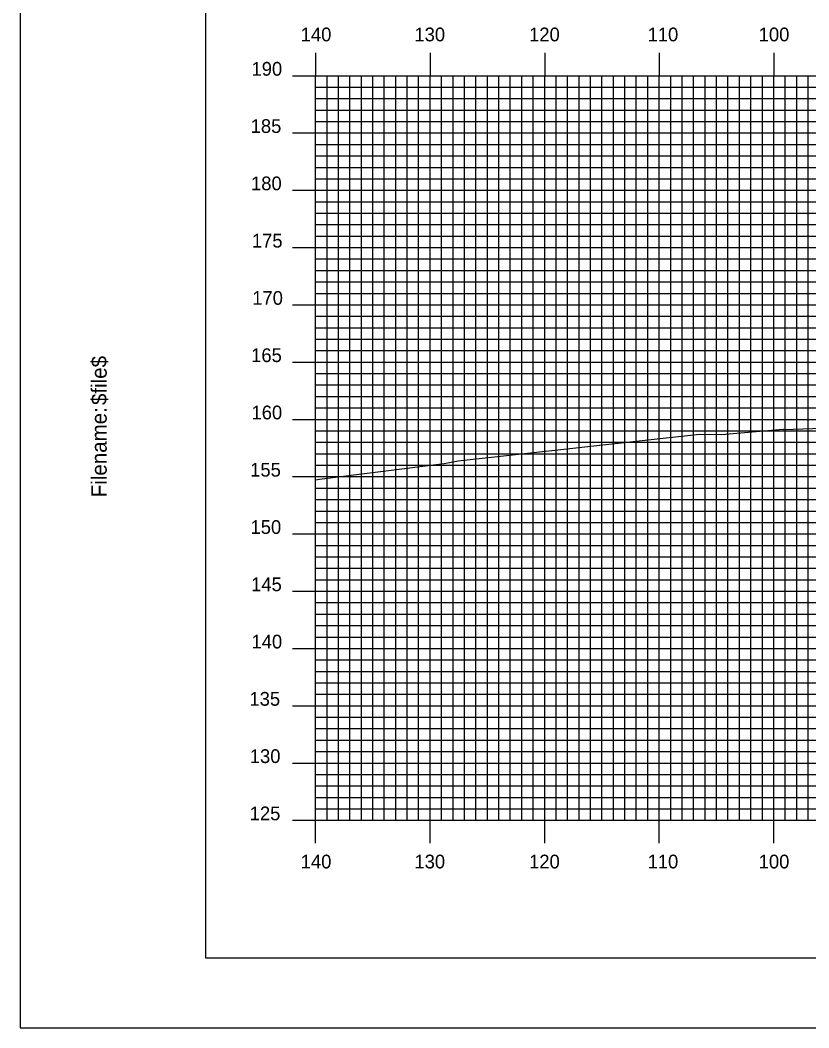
# Model space of a CAD drawing. Extents: x 1784615 to 1784958, y 442591 to 442811.
# Drawn here: x 1784614.7 to 1784683.6, y 442590.5 to 442678.5 of the extents above; entities that cross this region are included whole.
import ezdxf

# ---------------------------------------------------------------- set-up
doc = ezdxf.new("R2010")
doc.units = 0
for name, color, linetype in [('BORDER', 7, 'Continuous'), ('H_V ANNOTATION', 7, 'Continuous'), ('MAJOR', 7, 'Continuous'), ('MINOR', 7, 'Continuous'), ('PLOT BOUNDARY', 7, 'Continuous'), ('S_Roadway_Centerline', 7, 'Continuous')]:
    doc.layers.add(name, color=color, linetype=linetype)

msp = doc.modelspace()

# ---------------------------------------------------------------- linework, layer by layer
at = {"layer": 'BORDER'}
msp.add_lwpolyline([(1784630.912, 442596.665), (1784950.912, 442596.665), (1784950.912, 442806.665), (1784630.912, 442806.665)], close=True, dxfattribs=at)
at = {"layer": 'MAJOR'}
for p, q in [((1784640.512, 442675.669), (1784640.512, 442673.665)), ((1784650.512, 442675.669), (1784650.512, 442673.665)), ((1784660.512, 442675.669), (1784660.512, 442673.665)), ((1784670.512, 442675.669), (1784670.512, 442673.665)), ((1784680.512, 442675.669), (1784680.512, 442673.665)), ((1784638.508, 442673.665), (1784640.512, 442673.665)), ((1784640.512, 442673.665), (1784920.512, 442673.665)), ((1784640.512, 442608.665), (1784640.512, 442673.665)), ((1784640.512, 442608.665), (1784640.512, 442673.665)), ((1784640.512, 442673.665), (1784920.512, 442673.665)), ((1784650.512, 442608.665), (1784650.512, 442673.665)), ((1784660.512, 442608.665), (1784660.512, 442673.665)), ((1784670.512, 442608.665), (1784670.512, 442673.665)), ((1784680.512, 442608.665), (1784680.512, 442673.665)), ((1784638.508, 442668.665), (1784640.512, 442668.665)), ((1784640.512, 442668.665), (1784920.512, 442668.665)), ((1784638.508, 442663.665), (1784640.512, 442663.665)), ((1784640.512, 442663.665), (1784920.512, 442663.665)), ((1784638.508, 442658.665), (1784640.512, 442658.665)), ((1784640.512, 442658.665), (1784920.512, 442658.665)), ((1784638.508, 442653.665), (1784640.512, 442653.665)), ((1784640.512, 442653.665), (1784920.512, 442653.665)), ((1784638.508, 442648.665), (1784640.512, 442648.665)), ((1784640.512, 442648.665), (1784920.512, 442648.665)), ((1784638.508, 442643.665), (1784640.512, 442643.665)), ((1784640.512, 442643.665), (1784920.512, 442643.665)), ((1784638.508, 442638.665), (1784640.512, 442638.665)), ((1784640.512, 442638.665), (1784920.512, 442638.665)), ((1784638.508, 442633.665), (1784640.512, 442633.665)), ((1784640.512, 442633.665), (1784920.512, 442633.665)), ((1784638.508, 442628.665), (1784640.512, 442628.665)), ((1784640.512, 442628.665), (1784920.512, 442628.665)), ((1784638.508, 442623.665), (1784640.512, 442623.665)), ((1784640.512, 442623.665), (1784920.512, 442623.665)), ((1784638.508, 442618.665), (1784640.512, 442618.665)), ((1784640.512, 442618.665), (1784920.512, 442618.665)), ((1784638.508, 442613.665), (1784640.512, 442613.665)), ((1784640.512, 442613.665), (1784920.512, 442613.665)), ((1784638.508, 442608.665), (1784640.512, 442608.665)), ((1784640.512, 442608.665), (1784920.512, 442608.665)), ((1784640.512, 442606.661), (1784640.512, 442608.665)), ((1784650.512, 442606.661), (1784650.512, 442608.665)), ((1784660.512, 442606.661), (1784660.512, 442608.665)), ((1784670.512, 442606.661), (1784670.512, 442608.665)), ((1784680.512, 442606.661), (1784680.512, 442608.665))]:
    msp.add_line(p, q, dxfattribs=at)
at = {"layer": 'MINOR'}
for p, q in [((1784641.512, 442608.665), (1784641.512, 442673.665)), ((1784642.512, 442608.665), (1784642.512, 442673.665)), ((1784643.512, 442608.665), (1784643.512, 442673.665)), ((1784644.512, 442608.665), (1784644.512, 442673.665)), ((1784645.512, 442608.665), (1784645.512, 442673.665)), ((1784646.512, 442608.665), (1784646.512, 442673.665)), ((1784647.512, 442608.665), (1784647.512, 442673.665)), ((1784648.512, 442608.665), (1784648.512, 442673.665)), ((1784649.512, 442608.665), (1784649.512, 442673.665)), ((1784651.512, 442608.665), (1784651.512, 442673.665)), ((1784652.512, 442608.665), (1784652.512, 442673.665)), ((1784653.512, 442608.665), (1784653.512, 442673.665)), ((1784654.512, 442608.665), (1784654.512, 442673.665)), ((1784655.512, 442608.665), (1784655.512, 442673.665)), ((1784656.512, 442608.665), (1784656.512, 442673.665)), ((1784657.512, 442608.665), (1784657.512, 442673.665)), ((1784658.512, 442608.665), (1784658.512, 442673.665)), ((1784659.512, 442608.665), (1784659.512, 442673.665)), ((1784661.512, 442608.665), (1784661.512, 442673.665)), ((1784662.512, 442608.665), (1784662.512, 442673.665)), ((1784663.512, 442608.665), (1784663.512, 442673.665)), ((1784664.512, 442608.665), (1784664.512, 442673.665)), ((1784665.512, 442608.665), (1784665.512, 442673.665)), ((1784666.512, 442608.665), (1784666.512, 442673.665)), ((1784667.512, 442608.665), (1784667.512, 442673.665)), ((1784668.512, 442608.665), (1784668.512, 442673.665)), ((1784669.512, 442608.665), (1784669.512, 442673.665)), ((1784671.512, 442608.665), (1784671.512, 442673.665)), ((1784672.512, 442608.665), (1784672.512, 442673.665)), ((1784673.512, 442608.665), (1784673.512, 442673.665)), ((1784674.512, 442608.665), (1784674.512, 442673.665)), ((1784675.512, 442608.665), (1784675.512, 442673.665)), ((1784676.512, 442608.665), (1784676.512, 442673.665)), ((1784677.512, 442608.665), (1784677.512, 442673.665)), ((1784678.512, 442608.665), (1784678.512, 442673.665)), ((1784679.512, 442608.665), (1784679.512, 442673.665)), ((1784681.512, 442608.665), (1784681.512, 442673.665)), ((1784682.512, 442608.665), (1784682.512, 442673.665)), ((1784683.512, 442608.665), (1784683.512, 442673.665)), ((1784640.512, 442672.665), (1784920.512, 442672.665)), ((1784640.512, 442672.665), (1784642.516, 442672.665)), ((1784640.512, 442671.665), (1784920.512, 442671.665)), ((1784640.512, 442671.665), (1784642.516, 442671.665)), ((1784640.512, 442670.665), (1784920.512, 442670.665)), ((1784640.512, 442670.665), (1784642.516, 442670.665)), ((1784640.512, 442669.665), (1784920.512, 442669.665)), ((1784640.512, 442669.665), (1784642.516, 442669.665)), ((1784640.512, 442667.665), (1784920.512, 442667.665)), ((1784640.512, 442667.665), (1784642.516, 442667.665)), ((1784640.512, 442666.665), (1784920.512, 442666.665)), ((1784640.512, 442666.665), (1784642.516, 442666.665)), ((1784640.512, 442665.665), (1784642.516, 442665.665)), ((1784640.512, 442665.665), (1784920.512, 442665.665)), ((1784640.512, 442664.665), (1784920.512, 442664.665)), ((1784640.512, 442664.665), (1784642.516, 442664.665)), ((1784640.512, 442662.665), (1784920.512, 442662.665)), ((1784640.512, 442662.665), (1784642.516, 442662.665)), ((1784640.512, 442661.665), (1784920.512, 442661.665)), ((1784640.512, 442661.665), (1784642.516, 442661.665)), ((1784640.512, 442660.665), (1784920.512, 442660.665)), ((1784640.512, 442660.665), (1784642.516, 442660.665)), ((1784640.512, 442659.665), (1784920.512, 442659.665)), ((1784640.512, 442659.665), (1784642.516, 442659.665)), ((1784640.512, 442657.665), (1784920.512, 442657.665)), ((1784640.512, 442657.665), (1784642.516, 442657.665)), ((1784640.512, 442656.665), (1784920.512, 442656.665)), ((1784640.512, 442656.665), (1784642.516, 442656.665)), ((1784640.512, 442655.665), (1784920.512, 442655.665)), ((1784640.512, 442655.665), (1784642.516, 442655.665)), ((1784640.512, 442654.665), (1784920.512, 442654.665)), ((1784640.512, 442654.665), (1784642.516, 442654.665)), ((1784640.512, 442652.665), (1784920.512, 442652.665)), ((1784640.512, 442652.665), (1784642.516, 442652.665)), ((1784640.512, 442651.665), (1784920.512, 442651.665)), ((1784640.512, 442651.665), (1784642.516, 442651.665)), ((1784640.512, 442650.665), (1784920.512, 442650.665)), ((1784640.512, 442650.665), (1784642.516, 442650.665)), ((1784640.512, 442649.665), (1784920.512, 442649.665)), ((1784640.512, 442649.665), (1784642.516, 442649.665)), ((1784640.512, 442647.665), (1784920.512, 442647.665)), ((1784640.512, 442647.665), (1784642.516, 442647.665)), ((1784640.512, 442646.665), (1784920.512, 442646.665)), ((1784640.512, 442646.665), (1784642.516, 442646.665)), ((1784640.512, 442645.665), (1784920.512, 442645.665)), ((1784640.512, 442645.665), (1784642.516, 442645.665)), ((1784640.512, 442644.665), (1784920.512, 442644.665)), ((1784640.512, 442644.665), (1784642.516, 442644.665)), ((1784640.512, 442642.665), (1784920.512, 442642.665)), ((1784640.512, 442642.665), (1784642.516, 442642.665)), ((1784640.512, 442641.665), (1784920.512, 442641.665)), ((1784640.512, 442641.665), (1784642.516, 442641.665)), ((1784640.512, 442640.665), (1784920.512, 442640.665)), ((1784640.512, 442640.665), (1784642.516, 442640.665)), ((1784640.512, 442639.665), (1784920.512, 442639.665)), ((1784640.512, 442639.665), (1784642.516, 442639.665)), ((1784640.512, 442637.665), (1784920.512, 442637.665)), ((1784640.512, 442637.665), (1784642.516, 442637.665)), ((1784640.512, 442636.665), (1784920.512, 442636.665)), ((1784640.512, 442636.665), (1784642.516, 442636.665)), ((1784640.512, 442635.665), (1784920.512, 442635.665)), ((1784640.512, 442635.665), (1784642.516, 442635.665)), ((1784640.512, 442634.665), (1784920.512, 442634.665)), ((1784640.512, 442634.665), (1784642.516, 442634.665)), ((1784640.512, 442632.665), (1784920.512, 442632.665)), ((1784640.512, 442632.665), (1784642.516, 442632.665)), ((1784640.512, 442631.665), (1784920.512, 442631.665)), ((1784640.512, 442631.665), (1784642.516, 442631.665)), ((1784640.512, 442630.665), (1784920.512, 442630.665)), ((1784640.512, 442630.665), (1784642.516, 442630.665)), ((1784640.512, 442629.665), (1784920.512, 442629.665)), ((1784640.512, 442629.665), (1784642.516, 442629.665)), ((1784640.512, 442627.665), (1784920.512, 442627.665)), ((1784640.512, 442627.665), (1784642.516, 442627.665)), ((1784640.512, 442626.665), (1784920.512, 442626.665)), ((1784640.512, 442626.665), (1784642.516, 442626.665)), ((1784640.512, 442625.665), (1784920.512, 442625.665)), ((1784640.512, 442625.665), (1784642.516, 442625.665)), ((1784640.512, 442624.665), (1784920.512, 442624.665)), ((1784640.512, 442624.665), (1784642.516, 442624.665)), ((1784640.512, 442622.665), (1784920.512, 442622.665)), ((1784640.512, 442622.665), (1784642.516, 442622.665)), ((1784640.512, 442621.665), (1784920.512, 442621.665)), ((1784640.512, 442621.665), (1784642.516, 442621.665)), ((1784640.512, 442620.665), (1784920.512, 442620.665)), ((1784640.512, 442620.665), (1784642.516, 442620.665)), ((1784640.512, 442619.665), (1784920.512, 442619.665)), ((1784640.512, 442619.665), (1784642.516, 442619.665)), ((1784640.512, 442617.665), (1784920.512, 442617.665)), ((1784640.512, 442617.665), (1784642.516, 442617.665)), ((1784640.512, 442616.665), (1784920.512, 442616.665)), ((1784640.512, 442616.665), (1784642.516, 442616.665)), ((1784640.512, 442615.665), (1784920.512, 442615.665)), ((1784640.512, 442615.665), (1784642.516, 442615.665)), ((1784640.512, 442614.665), (1784920.512, 442614.665)), ((1784640.512, 442614.665), (1784642.516, 442614.665)), ((1784640.512, 442612.665), (1784920.512, 442612.665)), ((1784640.512, 442612.665), (1784642.516, 442612.665)), ((1784640.512, 442611.665), (1784920.512, 442611.665)), ((1784640.512, 442611.665), (1784642.516, 442611.665)), ((1784640.512, 442610.665), (1784920.512, 442610.665)), ((1784640.512, 442610.665), (1784642.516, 442610.665)), ((1784640.512, 442609.665), (1784920.512, 442609.665)), ((1784640.512, 442609.665), (1784642.516, 442609.665))]:
    msp.add_line(p, q, dxfattribs=at)
at = {"layer": 'PLOT BOUNDARY'}
msp.add_lwpolyline([(1784614.726, 442590.547), (1784954.726, 442590.547), (1784954.726, 442810.547), (1784614.726, 442810.547)], close=True, dxfattribs=at)
at = {"layer": 'S_Roadway_Centerline'}
msp.add_lwpolyline([(1784640.512, 442638.383), (1784640.858, 442638.432), (1784651.727, 442639.8), (1784652.969, 442640.058), (1784674.02, 442642.375), (1784675.952, 442642.334), (1784681.345, 442642.799), (1784681.373, 442642.787), (1784688.108, 442643.005)], dxfattribs=at)

# ---------------------------------------------------------------- texts
at = {"layer": 'BORDER'}
for s, p in [('$file$', (1784622.282, 442644.916)), ('$file$', (1784622.282, 442644.916)), ('Filename:', (1784622.282, 442636.862)), ('Filename:', (1784622.282, 442636.862))]:
    msp.add_text(s, height=1.3392, rotation=90, dxfattribs=at).set_placement(p)
at = {"layer": 'H_V ANNOTATION'}
for s, p in [('140', (1784639.217, 442676.665)), ('130', (1784649.142, 442676.665)), ('120', (1784659.153, 442676.665)), ('110', (1784669.496, 442676.665)), ('100', (1784679.196, 442676.665)), ('190', (1784634.922, 442673.665)), ('185', (1784634.847, 442668.665)), ('180', (1784634.879, 442663.665)), ('175', (1784634.954, 442658.665)), ('170', (1784634.986, 442653.665)), ('165', (1784634.89, 442648.665)), ('160', (1784634.922, 442643.665)), ('155', (1784634.804, 442638.665)), ('150', (1784634.836, 442633.665)), ('145', (1784634.89, 442628.665)), ('140', (1784634.922, 442623.665)), ('135', (1784634.74, 442618.665)), ('130', (1784634.772, 442613.665)), ('125', (1784634.762, 442608.665)), ('140', (1784639.217, 442604.465)), ('130', (1784649.142, 442604.465)), ('120', (1784659.153, 442604.465)), ('110', (1784669.496, 442604.465)), ('100', (1784679.196, 442604.465))]:
    msp.add_text(s, height=1.2, dxfattribs=at).set_placement(p)
at = {"layer": 'MAJOR'}
msp.add_text('-', height=0.012, dxfattribs=at).set_placement((1784640.504, 442608.665))

doc.saveas('drawing.dxf')
